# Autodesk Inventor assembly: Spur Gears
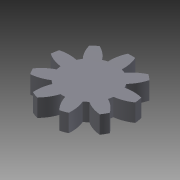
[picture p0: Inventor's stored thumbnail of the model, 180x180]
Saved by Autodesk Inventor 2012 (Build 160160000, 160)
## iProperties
Created: 2018-05
Part Number: Spur Gears
Document SubType Name: Assembly
Designer: Elkawokgy
Categories: <?xml version="1.0" encoding="UTF-16"?> <MemberInstance><Categories><FamilyTemplate/><ParamToTemplateMap><ParamToTemplate><ParamToTemplate CategoryParameter="//
ClientObjectVersion: 1
Author: Elkawokgy
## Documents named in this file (2)
- C:\Users\Elkawokgy\Downloads\New folder\Assembly1\Design Accelerator\Spur Gears1.iam
- C:\Users\Elkawokgy\Downloads\New folder\Assembly1\Design Accelerator\Spur Gear11.ipt
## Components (1 placed, 1 different names)
1. Spur Gear1:1
